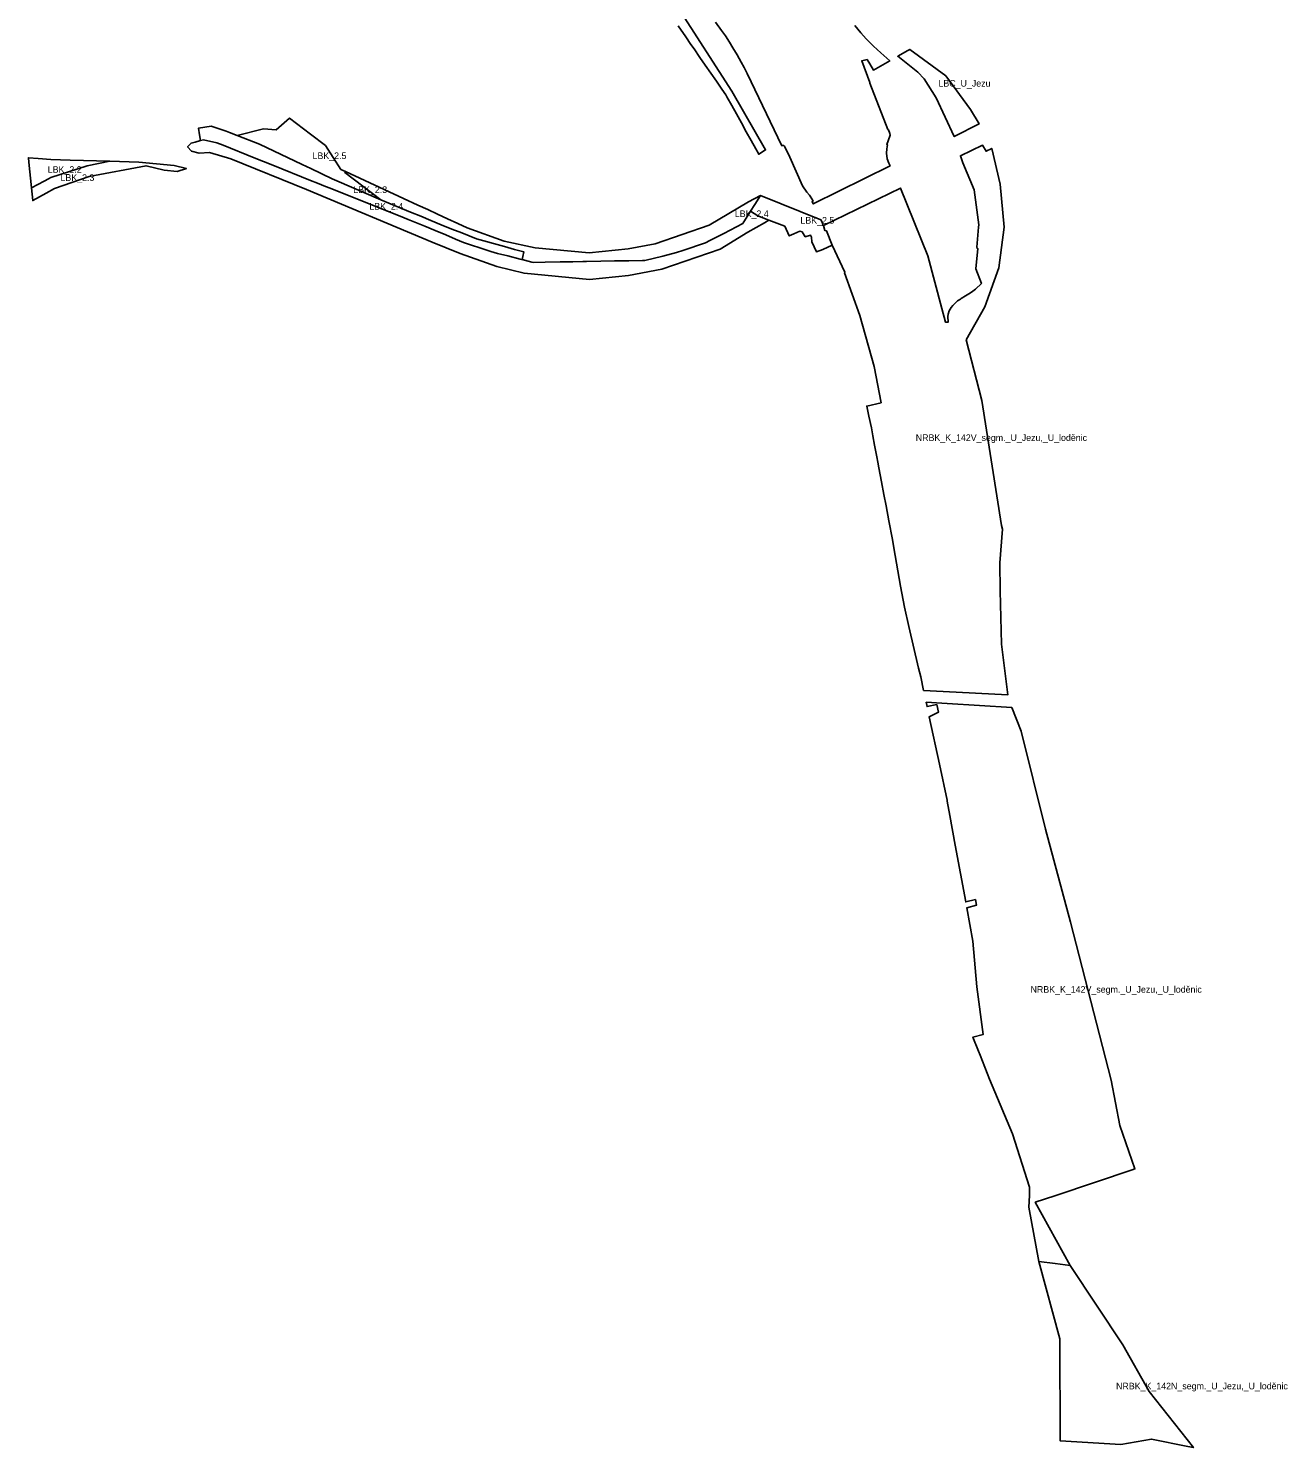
# Model space of a CAD drawing. Extents: x -535894 to -532763, y -1165802 to -1163647.
# Drawn here: x -533716 to -532763, y -1165802 to -1164727 of the extents above; entities that cross this region are included whole.
import ezdxf

# ---------------------------------------------------------------- set-up
doc = ezdxf.new("R2010")
doc.units = 0
for name, color, linetype in [('91230013', 7, 'Continuous'), ('91230023', 7, 'Continuous'), ('91270013', 7, 'Continuous'), ('91270023', 7, 'Continuous'), ('91280013', 7, 'Continuous'), ('91280023', 7, 'Continuous')]:
    doc.layers.add(name, color=color, linetype=linetype)

msp = doc.modelspace()

# ---------------------------------------------------------------- linework, layer by layer
at = {"layer": '91230013'}
for points in [[(-533038.193, -1165228.594), (-533040.38, -1165218.35), (-533041.97, -1165211.69), (-533049.49, -1165180.28), (-533052.58, -1165165.52), (-533055.7, -1165149.58), (-533060.76, -1165120.61), (-533061.85, -1165114.35), (-533064.51, -1165100.09), (-533066.59, -1165088.96), (-533068.21, -1165080.3), (-533070.04, -1165070.55), (-533072, -1165060.03), (-533072.81, -1165055.68), (-533073.57, -1165051.71), (-533075.28, -1165042.82), (-533076.61, -1165035.87), (-533077.78, -1165029.77), (-533079.658, -1165021.038), (-533081.32, -1165013.31), (-533070.375, -1165010.82), (-533075.69, -1164983.34), (-533086.39, -1164944.59), (-533098.11, -1164912.42), (-533097.896, -1164912.121), (-533097.918, -1164911.73), (-533107.544, -1164891.527), (-533111.8, -1164880.45), (-533113, -1164880.39), (-533113.94, -1164876.55), (-533055.68, -1164848.17), (-533035.02, -1164899.39), (-533024.33, -1164939.46), (-533021.57, -1164949.83), (-533019.65, -1164949.83), (-533019.75, -1164945.44), (-533019.74, -1164945.35), (-533019.5, -1164943.61), (-533018.74, -1164941.21), (-533017.27, -1164938.72), (-533016.06, -1164937.15), (-533014.17, -1164935.04), (-533012.47, -1164933.65), (-533010.36, -1164932.29), (-533009.67, -1164931.84), (-533006.56, -1164929.76), (-533003.92, -1164928.32), (-533001.85, -1164927.06), (-532998.95, -1164924.85), (-532994.46, -1164920.43), (-532998.63, -1164909.37), (-532997.02, -1164894.02), (-532997.55, -1164893.98), (-532997.96, -1164892.84), (-532996.596, -1164877.755), (-532996.43, -1164875.92), (-532999.79, -1164849.41), (-533008.53, -1164829.07), (-533010.27, -1164823.69), (-532993.57, -1164815.7), (-532990.84, -1164820.26), (-532986.56, -1164818.1), (-532980.17, -1164845.09), (-532977.31, -1164877.84), (-532981.22, -1164908.52), (-532991.79, -1164937.99), (-533005.91, -1164963.1), (-532994.2, -1165009.04), (-532979.21, -1165103.79), (-532978.36, -1165106.4), (-532980.41, -1165132.1), (-532980.24, -1165153.13), (-532979.22, -1165193.65), (-532975.089, -1165225.995), (-532974.335, -1165231.899), (-533023.406, -1165229.36)], [(-533036.286, -1165237.524), (-533020.388, -1165238.55), (-532971.48, -1165241.706), (-532964.21, -1165259.48), (-532945.97, -1165333.71), (-532926.98, -1165404.07), (-532896.21, -1165523.88), (-532889.53, -1165558.14), (-532878.16, -1165591.08), (-532880.194, -1165591.758), (-532908.13, -1165601.07), (-532938.91, -1165611.34), (-532953.65, -1165616.26), (-532927.21, -1165664.12), (-532938.47, -1165662.64), (-532951, -1165661.3), (-532958.57, -1165619.96), (-532957.99, -1165611.29), (-532958.061, -1165604.931), (-532970.84, -1165564.38), (-532986.264, -1165527.956), (-532988.358, -1165523.01), (-532995.402, -1165504.997), (-532996.663, -1165501.772), (-533000.91, -1165491.266), (-532993.193, -1165489.313), (-532997.81, -1165453.19), (-533000.89, -1165418.54), (-533005.488, -1165393.393), (-532998.242, -1165391.325), (-532999.025, -1165387.039), (-533006.318, -1165388.853), (-533014.2, -1165345.74), (-533018.3, -1165323.32), (-533020.29, -1165312.45), (-533020.4, -1165311.8), (-533026.24, -1165284.54), (-533033.915, -1165248.628), (-533026.975, -1165245.213), (-533028.21, -1165239.43), (-533035.573, -1165240.864)]]:
    msp.add_lwpolyline(points, close=True, dxfattribs=at)
at = {"layer": '91230023'}
msp.add_lwpolyline([(-532938.47, -1165662.64), (-532927.21, -1165664.12), (-532887.26, -1165724.36), (-532867.49, -1165759.55), (-532833.91, -1165802.16), (-532838.03, -1165801.32), (-532865.54, -1165795.7), (-532888.93, -1165799.76), (-532934.73, -1165797.08), (-532935.09, -1165719.88), (-532951, -1165661.3)], close=True, dxfattribs=at)
at = {"layer": '91270013'}
msp.add_lwpolyline([(-533090.161, -1164724.938), (-533085.762, -1164730.682), (-533081.802, -1164735.237), (-533076.175, -1164740.567), (-533070.523, -1164745.61), (-533063.86, -1164751.81), (-533076.17, -1164758.76), (-533079.04, -1164754), (-533080.974, -1164750.789), (-533085.07, -1164751.78), (-533078.92, -1164768.23), (-533078.96, -1164768.7), (-533065.26, -1164803.77), (-533064.85, -1164804.08), (-533063.85, -1164806.75), (-533063.41, -1164808.03), (-533064.98, -1164812.34), (-533066.05, -1164815.28), (-533065.52, -1164815.47), (-533066.12, -1164818.42), (-533066.32, -1164821.75), (-533065.88, -1164825.93), (-533064.62, -1164829.31), (-533063.56, -1164831.41), (-533121.79, -1164860.11), (-533122.6, -1164858.35), (-533121.94, -1164858.07), (-533122.39, -1164856.98), (-533124.52, -1164853.64), (-533126.75, -1164851.21), (-533129.85, -1164846.49), (-533139.39, -1164824.708), (-533143.209, -1164816.81), (-533143.6, -1164816.322), (-533144.251, -1164815.953), (-533144.641, -1164815.909), (-533145.227, -1164815.953), (-533145.683, -1164816.04), (-533171.85, -1164761.354), (-533174.141, -1164756.895), (-533176.389, -1164752.709), (-533179.464, -1164747.253), (-533182.674, -1164741.852), (-533185.298, -1164737.639), (-533188.351, -1164732.944), (-533191.148, -1164728.822), (-533195.682, -1164722.466)], dxfattribs=at)
msp.add_lwpolyline([(-533021.38, -1164763.26), (-533002.77, -1164788.53), (-532996.17, -1164799.59), (-533001.68, -1164802.19), (-533009.419, -1164806.211), (-533014.98, -1164809.1), (-533028.64, -1164779.86), (-533037.824, -1164765.421), (-533042.687, -1164760.287), (-533057.72, -1164748.344), (-533050.15, -1164744.07), (-533048.53, -1164743.15)], close=True, dxfattribs=at)
at = {"layer": '91270023'}
msp.add_lwpolyline([(-533224.07, -1164711.63), (-533183.34, -1164774.65), (-533157.83, -1164819.27), (-533163.04, -1164822.52), (-533165.34, -1164818.38), (-533168.77, -1164812.17), (-533172.45, -1164805.52), (-533176.14, -1164798.83), (-533179.93, -1164791.97), (-533183.43, -1164785.63), (-533187.14, -1164778.93), (-533187.91, -1164777.51), (-533190.93, -1164773.16), (-533195.08, -1164767.19), (-533199.21, -1164761.24), (-533203.5, -1164755.07), (-533207.59, -1164749.17), (-533212, -1164742.81), (-533214.36, -1164739.41), (-533218.37, -1164733.63), (-533224.16, -1164725.28)], dxfattribs=at)
at = {"layer": '91280013'}
for points in [[(-533541.19, -1164814.8), (-533557.97, -1164808.32), (-533538.206, -1164803.326), (-533528.49, -1164803.93), (-533518.46, -1164795.33), (-533502.549, -1164807.296), (-533491.019, -1164815.967), (-533479.52, -1164834.02), (-533476.1, -1164835.72), (-533476.589, -1164836.253), (-533449.329, -1164857.017), (-533482.547, -1164842.741), (-533485.98, -1164841.17), (-533502.187, -1164833.429), (-533508.929, -1164830.209)], [(-533568.75, -1164815.7), (-533545.15, -1164825.22), (-533531.09, -1164830.9), (-533502.39, -1164842.48), (-533497.24, -1164844.53), (-533491.23, -1164846.91), (-533487.68, -1164848.33), (-533431.47, -1164870.62), (-533428.43, -1164871.84), (-533423.51, -1164873.88), (-533415.86, -1164877.07), (-533408.04, -1164880.32), (-533400.11, -1164883.63), (-533392.63, -1164886.74), (-533386.52, -1164889.28), (-533381.38, -1164891.04), (-533373.49, -1164893.74), (-533369.05, -1164895.26), (-533365.96, -1164896.32), (-533360.93, -1164897.6), (-533353.15, -1164899.58), (-533343.76, -1164901.98), (-533334.89, -1164904.23), (-533333.91, -1164904.48), (-533324.7, -1164904.32), (-533313.39, -1164904.12), (-533303.94, -1164903.95), (-533296.3, -1164903.82), (-533293.4, -1164903.76), (-533282.57, -1164903.56), (-533272.33, -1164903.38), (-533261.52, -1164903.19), (-533251.03, -1164902.99), (-533249.36, -1164902.96), (-533235.8, -1164899.62), (-533225.42, -1164897.07), (-533220.52, -1164895.43), (-533203.49, -1164889.74), (-533200, -1164887.93), (-533189.49, -1164882.49), (-533175.17, -1164875.08), (-533169.319, -1164865.777), (-533163.824, -1164869.081), (-533155.355, -1164872.361), (-533158.808, -1164874.367), (-533171.4, -1164881.68), (-533192.2, -1164894.47), (-533236.41, -1164909.7), (-533261.61, -1164914.36), (-533291.28, -1164917.31), (-533340.78, -1164912.67), (-533361.33, -1164907.54), (-533389.23, -1164897.67), (-533410.4, -1164889.02), (-533505.42, -1164849.16), (-533562.74, -1164826), (-533578.89, -1164821.11), (-533586.7, -1164821.82), (-533592.59, -1164820.3), (-533595.59, -1164816.83), (-533592.91, -1164814.08), (-533589.91, -1164813.28), (-533585.817, -1164812.22), (-533583.58, -1164811.64), (-533573.32, -1164813.85)], [(-533603.37, -1164835.56), (-533613.25, -1164834.55), (-533626.96, -1164831.3), (-533670.19, -1164839.35), (-533696.31, -1164848.54), (-533702.752, -1164852.067), (-533712.834, -1164857.586), (-533713.818, -1164847.949), (-533704.29, -1164842.98), (-533700.79, -1164841.16), (-533699.02, -1164840.23), (-533671.59, -1164831.22), (-533654.486, -1164827.886), (-533632.378, -1164828.501), (-533605.839, -1164831.108), (-533596.46, -1164833.25)]]:
    msp.add_lwpolyline(points, close=True, dxfattribs=at)
at = {"layer": '91280023'}
for points in [[(-533508.929, -1164830.209), (-533502.187, -1164833.429), (-533485.98, -1164841.17), (-533482.547, -1164842.741), (-533449.329, -1164857.017), (-533432.806, -1164863.822), (-533426.826, -1164866.284), (-533418.937, -1164869.534), (-533411.249, -1164872.7), (-533403.421, -1164875.924), (-533395.416, -1164879.165), (-533387.877, -1164882.185), (-533376.769, -1164886.588), (-533368.48, -1164888.881), (-533363.81, -1164890.174), (-533355.604, -1164892.445), (-533347.953, -1164894.562), (-533340.838, -1164896.53), (-533341.727, -1164900.001), (-533342.327, -1164902.343), (-533343.76, -1164901.98), (-533353.15, -1164899.58), (-533360.93, -1164897.6), (-533365.96, -1164896.32), (-533369.05, -1164895.26), (-533373.49, -1164893.74), (-533381.38, -1164891.04), (-533386.52, -1164889.28), (-533392.63, -1164886.74), (-533400.11, -1164883.63), (-533408.04, -1164880.32), (-533415.86, -1164877.07), (-533423.51, -1164873.88), (-533428.43, -1164871.84), (-533431.47, -1164870.62), (-533487.68, -1164848.33), (-533491.23, -1164846.91), (-533497.24, -1164844.53), (-533502.39, -1164842.48), (-533531.09, -1164830.9), (-533545.15, -1164825.22), (-533568.75, -1164815.7), (-533573.32, -1164813.85), (-533583.58, -1164811.64), (-533585.817, -1164812.22), (-533586.49, -1164807.8), (-533587.26, -1164802.74), (-533577.82, -1164801.33), (-533566.47, -1164805.04), (-533563.91, -1164806.02), (-533557.97, -1164808.32), (-533541.19, -1164814.8)], [(-533713.818, -1164847.949), (-533714.571, -1164840.568), (-533715.547, -1164831.013), (-533716.102, -1164825.575), (-533716.135, -1164825.246), (-533708.69, -1164825.86), (-533699.25, -1164826.64), (-533684.543, -1164827.049), (-533654.486, -1164827.886), (-533671.59, -1164831.22), (-533699.02, -1164840.23), (-533700.79, -1164841.16), (-533704.29, -1164842.98)], [(-533235.8, -1164899.62), (-533249.36, -1164902.96), (-533251.03, -1164902.99), (-533261.52, -1164903.19), (-533272.33, -1164903.38), (-533282.57, -1164903.56), (-533293.4, -1164903.76), (-533296.3, -1164903.82), (-533303.94, -1164903.95), (-533313.39, -1164904.12), (-533324.7, -1164904.32), (-533333.91, -1164904.48), (-533334.89, -1164904.23), (-533342.327, -1164902.343), (-533341.727, -1164900.001), (-533340.838, -1164896.53), (-533347.953, -1164894.562), (-533355.604, -1164892.445), (-533363.81, -1164890.174), (-533368.48, -1164888.881), (-533376.769, -1164886.588), (-533387.877, -1164882.185), (-533395.416, -1164879.165), (-533403.421, -1164875.924), (-533411.249, -1164872.7), (-533418.937, -1164869.534), (-533426.826, -1164866.284), (-533432.806, -1164863.822), (-533449.329, -1164857.017), (-533476.589, -1164836.253), (-533476.1, -1164835.72), (-533432.125, -1164855.996), (-533421.201, -1164861.033), (-533413.65, -1164864.514), (-533406.222, -1164867.94), (-533398.688, -1164871.413), (-533390.995, -1164874.961), (-533383.775, -1164878.254), (-533355.854, -1164888.263), (-533332.237, -1164893.383), (-533291.404, -1164897.211), (-533261.946, -1164894.083), (-533241.514, -1164890.305), (-533200.695, -1164876.243), (-533170.75, -1164858.64), (-533161.703, -1164853.84), (-533166.05, -1164860.58), (-533169.319, -1164865.777), (-533175.17, -1164875.08), (-533189.49, -1164882.49), (-533200, -1164887.93), (-533203.49, -1164889.74), (-533220.52, -1164895.43), (-533225.42, -1164897.07)], [(-533166.05, -1164860.58), (-533161.703, -1164853.84), (-533116.02, -1164872.19), (-533114.81, -1164874.57), (-533114.4, -1164876.67), (-533113.94, -1164876.55), (-533113, -1164880.39), (-533111.8, -1164880.45), (-533107.544, -1164891.527), (-533114.4, -1164894.79), (-533119.37, -1164896.37), (-533122.912, -1164888.766), (-533123.175, -1164885.463), (-533123.831, -1164883.862), (-533127.88, -1164885.08), (-533128.683, -1164883.833), (-533130.27, -1164881.37), (-533131.844, -1164880.814), (-533136.46, -1164882.73), (-533139.96, -1164884.348), (-533143.352, -1164877.01), (-533155.355, -1164872.361), (-533163.824, -1164869.081), (-533169.319, -1164865.777)]]:
    msp.add_lwpolyline(points, close=True, dxfattribs=at)

# ---------------------------------------------------------------- texts
at = {"layer": '91230013'}
for p in [(-533044.1375, -1165039.7113), (-532957.223, -1165457.6152)]:
    msp.add_text('NRBK_K_142V_segm._U_Jezu,_U_loděnic', height=5, rotation=360, dxfattribs=at).set_placement(p)
at = {"layer": '91230023'}
msp.add_text('NRBK_K_142N_segm._U_Jezu,_U_loděnic', height=5, dxfattribs=at).set_placement((-532892.455, -1165758.0401))
at = {"layer": '91270013'}
msp.add_text('LBC_U_Jezu', height=5, rotation=360, dxfattribs=at).set_placement((-533026.945, -1164771.3131))
at = {"layer": '91280013'}
for s, rotation, p in [('LBK_2.5', 360, (-533500.9479, -1164826.1735)), ('LBK_2.3', 0, (-533691.8173, -1164842.736)), ('LBK_2.4', 0, (-533457.9388, -1164864.475))]:
    msp.add_text(s, height=5, rotation=rotation, dxfattribs=at).set_placement(p)
at = {"layer": '91280023'}
for s, rotation, p in [('LBK_2.2', 0, (-533701.4689, -1164836.5975)), ('LBK_2.3', 360, (-533470.1103, -1164851.8365)), ('LBK_2.4', 360, (-533181.1414, -1164870.1)), ('LBK_2.5', 0.0000001, (-533131.488, -1164875.105))]:
    msp.add_text(s, height=5, rotation=rotation, dxfattribs=at).set_placement(p)

doc.saveas('drawing.dxf')
